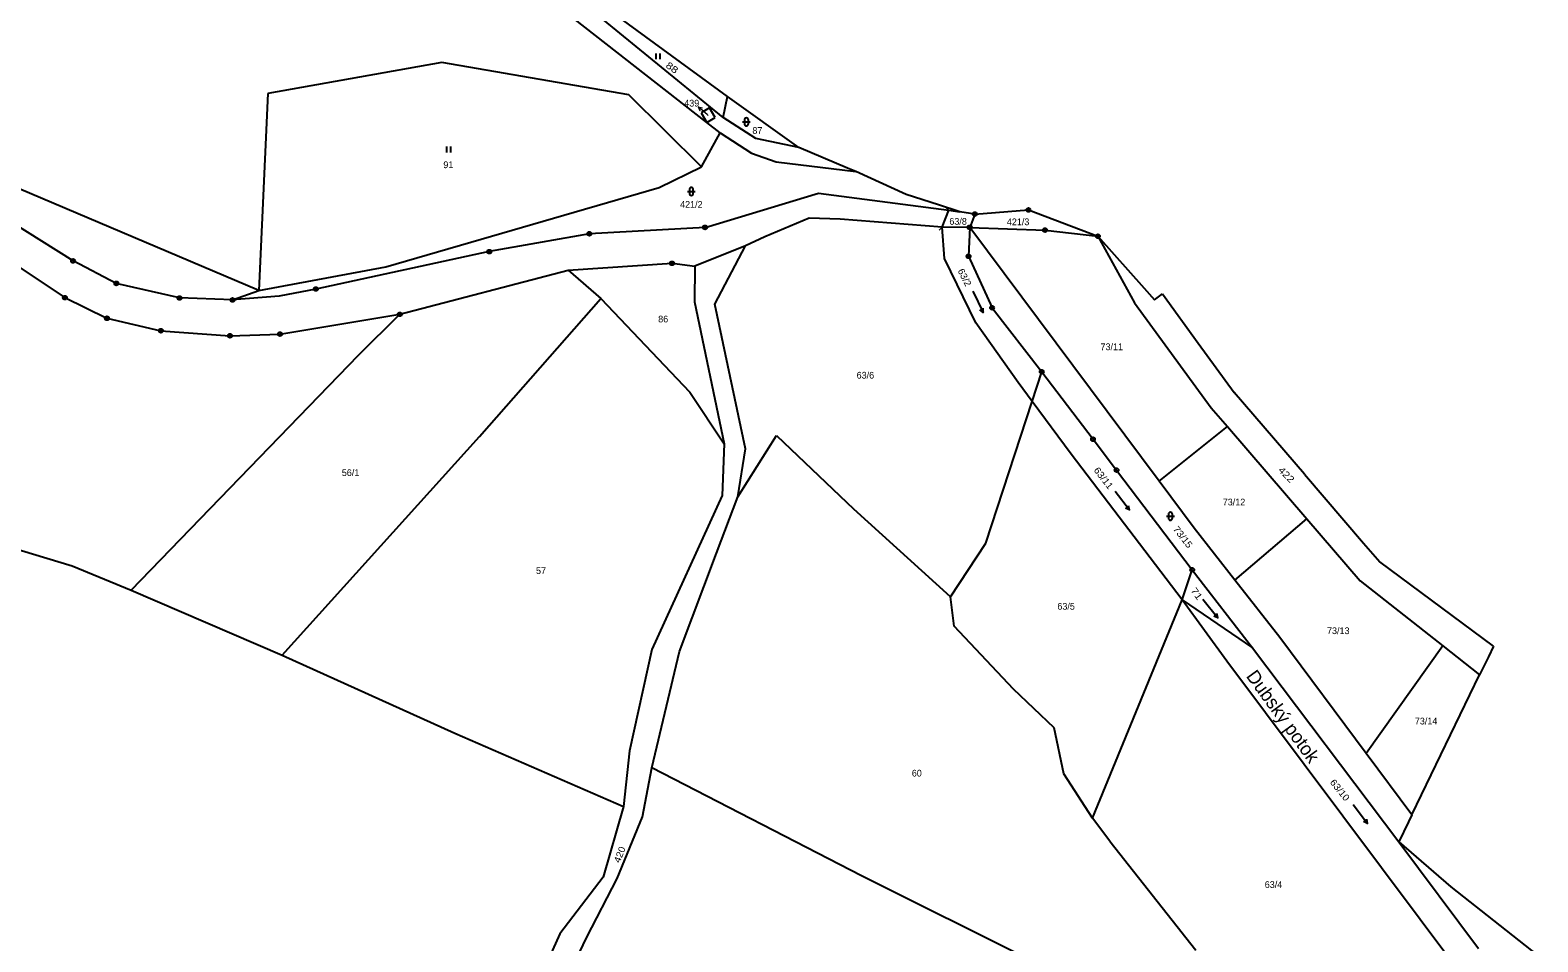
# Model space of a CAD drawing. Extents: x -791548 to -789311, y -1142631 to -1140855.
# Drawn here: x -789765.7 to -789384.5, y -1142399.2 to -1142168.7 of the extents above; entities that cross this region are included whole.
import ezdxf
from ezdxf.enums import TextEntityAlignment as Align

# ---------------------------------------------------------------- set-up
doc = ezdxf.new("R2010")
doc.units = 0
doc.header["$LTSCALE"] = 0.68
for name, color, linetype, lineweight in [('1', 7, 'Continuous', 25), ('3', 7, 'Continuous', 25), ('4', 7, 'Continuous', 13), ('7', 7, 'Continuous', 13), ('8', 7, 'Continuous', 25)]:
    doc.layers.add(name, color=color, linetype=linetype, lineweight=lineweight)
doc.layers.add('2', color=7, linetype='Continuous')

msp = doc.modelspace()

# ---------------------------------------------------------------- linework, layer by layer
at = {"layer": '1'}
for p, q in [((-789594.58, -1142192.03), (-789685.93, -1142120.56)), ((-789589.34, -1142185.48), (-789661.76, -1142132.44)), ((-789590.44, -1142190.77), (-789661.76, -1142132.44)), ((-789661.57, -1142176.86), (-789705.57, -1142184.71)), ((-789614.31, -1142185.02), (-789661.57, -1142176.86)), ((-789705.57, -1142184.71), (-789707.82, -1142234.54)), ((-789595.95, -1142203.26), (-789614.31, -1142185.02)), ((-789590.44, -1142190.77), (-789589.34, -1142185.48)), ((-789571.32, -1142198.36), (-789589.34, -1142185.48)), ((-789593.88, -1142188.34), (-789596.03, -1142189.63)), ((-789592.44, -1142190.74), (-789593.88, -1142188.34)), ((-789596.03, -1142189.63), (-789594.58, -1142192.03)), ((-789594.58, -1142192.03), (-789592.44, -1142190.74)), ((-789591.22, -1142194.66), (-789594.58, -1142192.03)), ((-789582.22, -1142196.11), (-789590.44, -1142190.77)), ((-789595.95, -1142203.26), (-789591.22, -1142194.66)), ((-789591.22, -1142194.66), (-789583.28, -1142199.8)), ((-789571.32, -1142198.36), (-789582.22, -1142196.11)), ((-789583.28, -1142199.8), (-789577.02, -1142202)), ((-789559, -1142203.54), (-789571.32, -1142198.36)), ((-789606.64, -1142208.46), (-789595.95, -1142203.26)), ((-789577.02, -1142202), (-789556.9, -1142204.42)), ((-789556.9, -1142204.42), (-789559, -1142203.54)), ((-789544.16, -1142210.25), (-789556.9, -1142204.42)), ((-789754.82, -1142227.02), (-789789.62, -1142205.2)), ((-789707.82, -1142234.54), (-789774.23, -1142206.36)), ((-789675.77, -1142228.51), (-789606.64, -1142208.46)), ((-789595.04, -1142218.55), (-789566.36, -1142209.93)), ((-789566.36, -1142209.93), (-789533.44, -1142214.23)), ((-789536.03, -1142212.83), (-789544.16, -1142210.25)), ((-789789.05, -1142214.87), (-789756.87, -1142236.32)), ((-789568.74, -1142216.21), (-789579.92, -1142220.98)), ((-789560.89, -1142216.5), (-789568.74, -1142216.21)), ((-789530.59, -1142214.58), (-789536.03, -1142212.83)), ((-789535.1, -1142218.53), (-789533.44, -1142214.23)), ((-789533.44, -1142214.23), (-789530.59, -1142214.58)), ((-789526.84, -1142215.18), (-789530.59, -1142214.58)), ((-789526.84, -1142215.18), (-789528.13, -1142218.55)), ((-789526.84, -1142215.18), (-789513.27, -1142214.14)), ((-789513.27, -1142214.14), (-789495.71, -1142220.78)), ((-789595.04, -1142218.55), (-789624.29, -1142220.16)), ((-789535.1, -1142218.53), (-789560.89, -1142216.5)), ((-789534.47, -1142226.42), (-789535.1, -1142218.53)), ((-789528.13, -1142218.55), (-789535.1, -1142218.53)), ((-789528.13, -1142218.55), (-789528.41, -1142225.86)), ((-789480.23, -1142282.75), (-789528.13, -1142218.55)), ((-789624.29, -1142220.16), (-789649.58, -1142224.69)), ((-789584.82, -1142223.2), (-789597.61, -1142228.39)), ((-789592.54, -1142237.94), (-789584.82, -1142223.2)), ((-789579.92, -1142220.98), (-789584.82, -1142223.2)), ((-789495.71, -1142220.78), (-789484.06, -1142233.95)), ((-789495.71, -1142220.78), (-789486.48, -1142237.66)), ((-789743.88, -1142232.71), (-789754.82, -1142227.02)), ((-789649.58, -1142224.69), (-789693.42, -1142234.13)), ((-789629.63, -1142229.41), (-789603.38, -1142227.64)), ((-789603.38, -1142227.64), (-789597.61, -1142228.39)), ((-789526.6, -1142242.71), (-789534.47, -1142226.42)), ((-789528.41, -1142225.86), (-789522.47, -1142238.88)), ((-789707.82, -1142234.54), (-789675.77, -1142228.51)), ((-789672.21, -1142240.53), (-789629.63, -1142229.41)), ((-789629.63, -1142229.41), (-789621.37, -1142236.56)), ((-789597.61, -1142228.39), (-789597.73, -1142237.37)), ((-789727.88, -1142236.4), (-789743.88, -1142232.71)), ((-789714.5, -1142236.9), (-789707.82, -1142234.54)), ((-789693.42, -1142234.13), (-789702.67, -1142235.97)), ((-789484.06, -1142233.95), (-789481.42, -1142236.88)), ((-789756.87, -1142236.32), (-789746.25, -1142241.53)), ((-789714.5, -1142236.9), (-789727.88, -1142236.4)), ((-789702.67, -1142235.97), (-789714.5, -1142236.9)), ((-789652.1, -1142271.4), (-789621.37, -1142236.56)), ((-789621.37, -1142236.56), (-789598.86, -1142260.24)), ((-789597.73, -1142237.37), (-789590.18, -1142273.28)), ((-789584.83, -1142274.51), (-789592.54, -1142237.94)), ((-789522.47, -1142238.88), (-789509.9, -1142255.05)), ((-789486.48, -1142237.66), (-789467.08, -1142264.19)), ((-789481.42, -1142236.88), (-789479.4, -1142235.32)), ((-789479.4, -1142235.32), (-789470.34, -1142247.81)), ((-789746.25, -1142241.53), (-789732.6, -1142244.68)), ((-789702.5, -1142245.54), (-789672.21, -1142240.53)), ((-789682.64, -1142250.87), (-789672.21, -1142240.53)), ((-789515.9, -1142257.75), (-789526.6, -1142242.71)), ((-789732.6, -1142244.68), (-789715.15, -1142245.95)), ((-789715.15, -1142245.95), (-789702.5, -1142245.54)), ((-789470.34, -1142247.81), (-789461.27, -1142260.3)), ((-789740.14, -1142310.29), (-789682.64, -1142250.87)), ((-789512.35, -1142262.55), (-789515.9, -1142257.75)), ((-789512.35, -1142262.55), (-789509.9, -1142255.05)), ((-789509.9, -1142255.05), (-789496.95, -1142272.11)), ((-789598.86, -1142260.24), (-789590.18, -1142273.28)), ((-789443.51, -1142280.97), (-789461.27, -1142260.3)), ((-789524.04, -1142298.43), (-789512.35, -1142262.55)), ((-789502.48, -1142275.87), (-789512.35, -1142262.55)), ((-789467.08, -1142264.19), (-789462.99, -1142268.93)), ((-789480.23, -1142282.75), (-789462.99, -1142268.93)), ((-789462.99, -1142268.93), (-789442.9, -1142292.23)), ((-789701.99, -1142326.74), (-789652.1, -1142271.4)), ((-789590.18, -1142273.28), (-789590.69, -1142286.34)), ((-789586.72, -1142286.69), (-789577, -1142271.17)), ((-789577, -1142271.17), (-789557.41, -1142289.76)), ((-789496.95, -1142272.11), (-789491.01, -1142279.93)), ((-789586.72, -1142286.69), (-789584.83, -1142274.51)), ((-789474.45, -1142312.76), (-789502.48, -1142275.87)), ((-789491.01, -1142279.93), (-789471.88, -1142305.13)), ((-789443.51, -1142280.97), (-789428.57, -1142298.35)), ((-789590.69, -1142286.34), (-789608.49, -1142325.28)), ((-789592.15, -1142300.94), (-789586.72, -1142286.69)), ((-789796.14, -1142291.81), (-789755.01, -1142304.11)), ((-789532.97, -1142311.95), (-789557.41, -1142289.76)), ((-789461.06, -1142307.75), (-789442.9, -1142292.23)), ((-789442.9, -1142292.23), (-789429.41, -1142307.88)), ((-789532.97, -1142311.95), (-789524.04, -1142298.43)), ((-789428.57, -1142298.35), (-789424.45, -1142303.15)), ((-789601.51, -1142325.77), (-789592.15, -1142300.94)), ((-789395.69, -1142324.44), (-789424.45, -1142303.15)), ((-789755.01, -1142304.11), (-789740.14, -1142310.29)), ((-789474.45, -1142312.76), (-789471.88, -1142305.13)), ((-789471.88, -1142305.13), (-789456.66, -1142324.85)), ((-789740.14, -1142310.29), (-789701.99, -1142326.74)), ((-789429.41, -1142307.88), (-789408.49, -1142324.37)), ((-789532.06, -1142319.37), (-789532.97, -1142311.95)), ((-789497.08, -1142367.89), (-789474.45, -1142312.76)), ((-789463.16, -1142328.26), (-789474.45, -1142312.76)), ((-789474.45, -1142312.76), (-789456.66, -1142324.85)), ((-789517.02, -1142335.34), (-789532.06, -1142319.37)), ((-789701.99, -1142326.74), (-789658.26, -1142346.39)), ((-789608.49, -1142325.28), (-789614.14, -1142350.87)), ((-789608.49, -1142355.16), (-789601.51, -1142325.77)), ((-789456.66, -1142324.85), (-789419.67, -1142373.91)), ((-789408.49, -1142324.37), (-789427.89, -1142351.53)), ((-789408.49, -1142324.37), (-789399.2, -1142331.69)), ((-789395.69, -1142324.44), (-789396.99, -1142327.12)), ((-789404.46, -1142406.59), (-789463.16, -1142328.26)), ((-789396.99, -1142327.12), (-789399.2, -1142331.69)), ((-789416.35, -1142367.06), (-789399.2, -1142331.69)), ((-789506.79, -1142345.08), (-789517.02, -1142335.34)), ((-789504.31, -1142356.68), (-789506.79, -1142345.08)), ((-789658.26, -1142346.39), (-789615.66, -1142364.95)), ((-789614.14, -1142350.87), (-789615.66, -1142364.95)), ((-789416.35, -1142367.06), (-789427.89, -1142351.53)), ((-789610.86, -1142367.61), (-789608.49, -1142355.16)), ((-789555.5, -1142382.48), (-789608.49, -1142355.16)), ((-789497.08, -1142367.89), (-789504.31, -1142356.68)), ((-789615.66, -1142364.95), (-789620.79, -1142382.87)), ((-789617.24, -1142383.18), (-789610.86, -1142367.61)), ((-789492.74, -1142373.77), (-789497.08, -1142367.89)), ((-789416.35, -1142367.06), (-789417.21, -1142368.84)), ((-789417.21, -1142368.84), (-789419.67, -1142373.91)), ((-789492.74, -1142373.77), (-789470.94, -1142401.32)), ((-789419.67, -1142373.91), (-789399.48, -1142400.85)), ((-789419.67, -1142373.91), (-789406.47, -1142385.27)), ((-789620.79, -1142382.87), (-789631.79, -1142397.15)), ((-789624.96, -1142398.03), (-789617.24, -1142383.18)), ((-789512.08, -1142404.14), (-789555.5, -1142382.48)), ((-789406.47, -1142385.27), (-789394.07, -1142395.09)), ((-789394.07, -1142395.09), (-789384.49, -1142402.67)), ((-789631.79, -1142397.15), (-789644.1, -1142424.79)), ((-789638.91, -1142427.38), (-789624.96, -1142398.03))]:
    msp.add_line(p, q, dxfattribs=at)
for points in [[(-789528.13, -1142218.55), (-789509.09, -1142219.23), (-789495.71, -1142220.78)], [(-789461.06, -1142307.75), (-789471.38, -1142294.61), (-789480.23, -1142282.75)], [(-789427.89, -1142351.53), (-789449.69, -1142322.22), (-789461.06, -1142307.75)]]:
    msp.add_lwpolyline(points, dxfattribs=at)
at = {"layer": '3'}
for p, q in [((-789607.361, -1142176.05), (-789607.361, -1142174.55)), ((-789606.36, -1142176.05), (-789606.36, -1142174.55)), ((-789585.591, -1142191.881), (-789583.589, -1142191.881)), ((-789585.091, -1142191.381), (-789585.091, -1142192.382)), ((-789584.089, -1142192.382), (-789584.089, -1142191.381)), ((-789660.331, -1142199.59), (-789660.331, -1142198.09)), ((-789659.33, -1142199.59), (-789659.33, -1142198.09)), ((-789599.501, -1142209.461), (-789597.499, -1142209.461)), ((-789599.001, -1142208.961), (-789599.001, -1142209.962)), ((-789597.999, -1142209.962), (-789597.999, -1142208.961)), ((-789524.725, -1142240.066), (-789525.604, -1142239.407)), ((-789487.761, -1142290.005), (-789488.75, -1142289.526)), ((-789478.381, -1142291.581), (-789476.379, -1142291.581)), ((-789477.881, -1142291.081), (-789477.881, -1142292.082)), ((-789476.879, -1142292.082), (-789476.879, -1142291.081)), ((-789465.428, -1142317.25), (-789466.433, -1142316.806)), ((-789427.561, -1142369.265), (-789428.55, -1142368.786))]:
    msp.add_line(p, q, dxfattribs=at)
for points in [[(-789527.355, -1142234.673), (-789524.725, -1142240.066), (-789524.703, -1142238.967)], [(-789491.372, -1142285.213), (-789487.761, -1142290.005), (-789487.949, -1142288.923)], [(-789469.204, -1142312.587), (-789465.428, -1142317.25), (-789465.653, -1142316.175)], [(-789431.172, -1142364.473), (-789427.561, -1142369.265), (-789427.749, -1142368.183)]]:
    msp.add_lwpolyline(points, dxfattribs=at)
for centre, start, end in [((-789584.59, -1142191.3809), 0, 180), ((-789584.59, -1142192.3809), 180, 359.98789), ((-789598.5, -1142208.9609), 0, 180), ((-789598.5, -1142209.9609), 180, 359.98789), ((-789477.38, -1142291.0809), 0, 180), ((-789477.38, -1142292.0809), 180, 359.98789)]:
    msp.add_arc(centre, 0.5, start, end, dxfattribs=at)
at = {"layer": '4'}
for p, q in [((-789534.147, -1142213.522), (-789533.44, -1142214.229)), ((-789535.808, -1142219.237), (-789535.101, -1142218.53)), ((-789527.423, -1142219.258), (-789528.13, -1142218.551))]:
    msp.add_line(p, q, dxfattribs=at)
at = {"layer": '7'}
msp.add_line((-789596.809, -1142188.051), (-789596.364, -1142189.078), dxfattribs=at)
msp.add_lwpolyline([(-789594.22, -1142190.23), (-789594.51, -1142189.98), (-789596.809, -1142188.051), (-789595.72, -1142188.311)], dxfattribs=at)
at = {"layer": '8'}
for centre, radius in [((-789526.84, -1142215.1799), 0.5), ((-789526.84, -1142215.1799), 0.0303), ((-789513.27, -1142214.1399), 0.5), ((-789513.27, -1142214.1399), 0.0303), ((-789624.2899, -1142220.16), 0.5), ((-789595.0399, -1142218.55), 0.5), ((-789595.0399, -1142218.55), 0.0303), ((-789528.13, -1142218.5499), 0.5), ((-789528.13, -1142218.5499), 0.0303), ((-789509.09, -1142219.2299), 0.5), ((-789509.09, -1142219.2299), 0.0303), ((-789624.2899, -1142220.16), 0.0303), ((-789495.71, -1142220.7799), 0.5), ((-789495.71, -1142220.7799), 0.0303), ((-789754.8199, -1142227.02), 0.5), ((-789754.8199, -1142227.02), 0.0303), ((-789649.5799, -1142224.69), 0.5), ((-789649.5799, -1142224.69), 0.0303), ((-789603.3799, -1142227.64), 0.5), ((-789603.3799, -1142227.64), 0.0303), ((-789528.41, -1142225.8599), 0.5), ((-789528.41, -1142225.8599), 0.0303), ((-789743.8799, -1142232.71), 0.5), ((-789743.8799, -1142232.71), 0.0303), ((-789693.4199, -1142234.13), 0.5), ((-789693.4199, -1142234.13), 0.0303), ((-789756.8699, -1142236.32), 0.5), ((-789756.8699, -1142236.32), 0.0303), ((-789727.8799, -1142236.4), 0.5), ((-789727.8799, -1142236.4), 0.0303), ((-789714.4999, -1142236.9), 0.5), ((-789714.4999, -1142236.9), 0.0303), ((-789522.47, -1142238.8799), 0.5), ((-789522.47, -1142238.8799), 0.0303), ((-789746.2499, -1142241.53), 0.5), ((-789746.2499, -1142241.53), 0.0303), ((-789672.2099, -1142240.53), 0.5), ((-789672.2099, -1142240.53), 0.0303), ((-789732.5999, -1142244.68), 0.5), ((-789732.5999, -1142244.68), 0.0303), ((-789715.1499, -1142245.95), 0.5), ((-789715.1499, -1142245.95), 0.0303), ((-789702.4999, -1142245.54), 0.5), ((-789702.4999, -1142245.54), 0.0303), ((-789509.9, -1142255.0499), 0.5), ((-789509.9, -1142255.0499), 0.0303), ((-789496.95, -1142272.1099), 0.5), ((-789496.95, -1142272.1099), 0.0303), ((-789491.01, -1142279.9299), 0.5), ((-789491.01, -1142279.9299), 0.0303), ((-789471.88, -1142305.1299), 0.5), ((-789471.88, -1142305.1299), 0.0303)]:
    msp.add_circle(centre, radius, dxfattribs=at)

# ---------------------------------------------------------------- texts
at = {"layer": '2'}
for s, rotation, width, p in [('88', 324, 1.25, (-789603.8686, -1142178.8619)), ('63/2', 297, 1.05, (-789530.1686, -1142231.5886)), ('63/11', 308, 1.1, (-789494.9655, -1142282.4577)), ('422', 315, 1.2, (-789448.6635, -1142281.6865)), ('73/15', 308, 1.1, (-789474.9055, -1142297.3477)), ('71', 305, 1.25, (-789471.4464, -1142311.6435)), ('63/10', 309, 1.1, (-789435.1995, -1142361.3496)), ('420', 68, 1.1, (-789615.8351, -1142377.4474))]:
    msp.add_text(s, height=1.7, rotation=rotation, dxfattribs=dict(at, width=width)).set_placement(p, align=Align.CENTER)
for s, p in [('439', (-789598.409, -1142187.995)), ('87', (-789581.809, -1142194.912)), ('91', (-789659.939, -1142203.572)), ('421/2', (-789598.5, -1142213.592)), ('63/8', (-789531.059, -1142217.892)), ('421/3', (-789515.89, -1142218.005)), ('86', (-789605.619, -1142242.572)), ('73/11', (-789492.22, -1142249.595)), ('63/6', (-789554.499, -1142256.782)), ('56/1', (-789684.659, -1142281.422)), ('73/12', (-789461.31, -1142288.845)), ('57', (-789636.509, -1142306.192)), ('63/5', (-789503.749, -1142315.212)), ('73/13', (-789434.95, -1142321.385)), ('73/14', (-789412.75, -1142344.225)), ('60', (-789541.499, -1142357.392)), ('63/4', (-789451.319, -1142385.552))]:
    msp.add_text(s, height=1.7, dxfattribs=at).set_placement(p, align=Align.CENTER)
at = {"layer": '7'}
msp.add_text('Dubský potok', height=3.4, rotation=306, dxfattribs=at).set_placement((-789458.377, -1142332.039))

doc.saveas('drawing.dxf')
